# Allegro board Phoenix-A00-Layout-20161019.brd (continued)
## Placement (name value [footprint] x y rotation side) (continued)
D41  BAT54A-7-F_200mA  [SOT23_123]  225.41 246.13 90 top
DA4  AZ5125-02S.R7G  [SOT23_123]  192.44 12.91 0 top
DA5  AZ5125-02S.R7G  [SOT23_123]  171.86 24.72 180 top
DA6  AZ5125-02S.R7G  [SOT23_123]  232.32 243.41 180 top
DA7  AZ5125-01H  [SOD_523]  197.39 18.37 270 top
DF1  1N4148W-7-F_150mA  [SOD123]  198.66 222 180 top
DG1  BAV99-7-F_300mA  [SOT23_123]  162.99 229.87 90 top
DG2  BAV99-7-F_300mA  [SOT23_123]  169.85 229.87 90 top
DG3  BAV99-7-F_300mA  [SOT23_123]  166.42 229.87 90 top
DG4  1N4148W-7-F_150mA  [SOD123]  188.25 235.84 180 top
DG5  BAV99-7-F_300mA  [SOT23_123]  159.55 235.59 90 top
DG6  BAV99-7-F_300mA  [SOT23_123]  159.55 231.78 90 top
DG7  BAV99-7-F_300mA  [SOT23_123]  172.77 232.66 0 top
DG8  BAV99-7-F_300mA  [SOT23_123]  173.28 228.87 90 top
DIMM1  DDR IV_288P_15u_Black  [DDR4_288_67_5591X256]  223.94 91.72 180 top
DIMM2  DDR IV_288P_15u_Black  [DDR4_288_67_5591X256]  223.94 82.72 180 top
DO1  B0540W-7-F_0.5A  [SOD123_H57]  201.58 41.53 0 top
DO2  1N4148W-7-F_150mA  [SOD123]  182.41 235.84 180 top
DO3  1N4148W-7-F_150mA  [SOD123]  178.21 223.77 180 top
ECK1  470uF_EC_6.3V  [CE25D63H125]  31.15 170.31 0 top
ECK3  470uF_EC_6.3V  [CE25D63H125]  49.69 220.85 0 top
ECK4  120uF_EC_16V  [CE25D63H125]  71.03 237.74 0 top
ECK5  470uF_EC_6.3V  [CE25D63H125]  31.53 231.01 0 top
ECK6  470uF_EC_6.3V  [CE25D63H125]  31.78 216.92 0 top
ECK7  120uF_EC_16V  [CE25D63H125]  31.53 243.33 0 top
ECU2  470uF_EC_6.3V  [CE25D63H125]  138.29 230.76 0 top
ECU3  470uF_EC_6.3V  [CE25D63H125]  142.48 236.85 0 top
ECU6  220uF_EC_10V  [CE25D63H125]  132.44 19.93 0 top
ECU7  220uF_EC_10V  [CE25D63H125]  132.37 26.8 0 top
ECU9  470uF_EC_6.3V  [CE25D63H125]  59.22 69.93 0 top
ECU10  220uF_EC_10V  [CE25D63H125]  156.29 21.1 0 top
ECU13  470uF_EC_6.3V  [CE25D63H125]  98.03 251.33 0 top
ECX7  220uF_EC_16V  [CE25D63H125]  70.14 244.86 0 top
ECX10  470uF_EC_16V  [CE35D80H130]  50.83 238.25 0 top
ECX11  470uF_EC_6.3V  [CE25D63H125]  71.28 230.89 0 top
ECX12  220uF_EC_10V  [CE25D63H125]  71.28 224.03 0 top
EEPROM_G  M24C01-WMN6TP  [SOP8JA]  164.01 225.04 90 top
F2  1.5A_6V  [FS_70_83X53]  225.54 250.32 270 top
F6  1.5A_6V  [FS_70_83X53]  163.96 238.99 180 top
F_AUDIO  HDA_X1_GF_Black  [AUDIO_6_374X463]  186.32 12.64 180 top
F_USB2  USBX2_GF_Black  [USB4X2]  164.75 10.62 180 top
F_USB3  USB3X2_15u_Blue  [USB3X4_18_79]  143.75 13.01 0 top
FAN_CPU  Header_1X4_GF_Ivory  [HFAN_4_100_400X225_P2]  238.29 133.22 270 top
FAN_SYS  FAN_3P_T_Brown  [HFAN_3_100_300X224_C2]  197.01 227.35 0 top
FBA1  600_500mA  [0603_H37]  195.36 19.64 180 top
FBA2  600_500mA  [0603_H37]  195.36 20.91 180 top
FBA3  80_3A  [0805]  195.11 24.34 180 top
FBA4  600_500mA  [0603_H37]  188.63 31.83 0 top
FBA5  600_500mA  [0603_H37]  195.36 22.18 180 top
FBG1  600_1A  [0603_H37]  144.81 232.54 270 top
FBG2  600_1A  [0603]  155.75 219.84 180 top
FBK1  600_500mA  [0603]  65.95 182.88 180 top
FBK3  600_500mA  [0603]  51.6 184.15 90 top
FG1  1.1A_6V  [FS1311_H28]  201.46 247.14 90 top
FM1  MTG/ID4/OD7  [FD40]  28.61 252.98 0 top
FM2  MTG/ID4/OD7  [FD40]  5.7 41.48 180 bottom
FM3  MTG/ID4/OD7  [FD40]  28.61 252.98 180 bottom
FM4  MTG/ID4/OD7  [FD40]  230.23 26.49 180 bottom
FM5  MTG/ID4/OD7  [FD40]  5.14 39.47 0 top
FM7  MTG/ID4/OD7  [FD40]  229.27 25.4 0 top
FU2  3A_6V  [FS0805]  143.92 241.43 180 top
FU5  3A_6V  [FS0805]  154.21 11.64 270 top
FU6  3A_6V  [FS0805]  134.4 7.7 90 top
FU9  3A_6V  [FS0805]  64.93 70.1 0 top
FVS  TEST POINT  [FVS_DELL]  70.01 105.28 270 top
HDD_LED  LED ASSEMBLY_White  [LED_2_90_201X260]  197.5 10.97 0 top
HDMI  HDMI_R_19P_15u_Black  [HDMI_19_59_591X492]  211.29 248.13 180 top
HS_CLIP1  CLIP_2P  [HB9003]  38.97 147.34 270 top
HS_CLIP2  CLIP_2P  [HB9003]  75.57 101.58 270 top
INT_SPKR  Header_1X4_GF_Ivory  [HF5504]  163.28 53.29 0 top
IO_FBI7  120_3A  [0603]  175.67 24.21 180 top
IO_FBI8  120_3A  [0603]  175.67 25.48 180 top
IO_FBI9  60_3A  [0603_H37]  189.64 10.75 90 top
IO_FBI10  60_3A  [0603_H37]  188.37 10.75 90 top
IO_FBI11  60_3A  [0603_H37]  237.78 244.47 180 top
IO_FBI12  60_3A  [0603_H37]  237.78 243.08 180 top
IO_FBI13  100_2A  [0603_H37]  163.63 49.94 270 top
IO_FBI14  100_2A  [0603_H37]  165.03 49.94 270 top
KYBD_MOUSE  PS2-KBMS-2_GF  [PS2X2]  156.19 254.52 0 top
L13  120_400mA  [0603]  154.84 235.55 270 top
L14  120_400mA  [0603]  152.3 235.55 270 top
L15  120_400mA  [0603]  156.11 235.55 270 top
L16  120_400mA  [0603]  153.57 235.55 270 top
L60  2.2uH_115mA  [0603]  54.39 147.07 270 top
L61  2.2uH_115mA  [0603]  70.9 109.09 180 top
L62  2.2uH_115mA  [0603]  64.8 143 0 top
LG1  22_600mA  [0603_H37]  168.7 234.95 180 top
LG2  22_600mA  [0603_H37]  165.91 234.95 180 top
LG3  22_600mA  [0603_H37]  163.12 234.95 180 top
LL2  4.7uH_1A/1.35A  [1212H59]  117.89 221.23 270 top
LPC_DEBUG  Header_2X7_K10_GF_Black  [HH_2X7_79_O10]  7.91 156.08 270 top
LU1  CMC_90_330mA  [L4S12X20V_H43]  97.52 246.51 180 top
LU2  CMC_90_330mA  [L4S12X20V_H43]  97.52 243.97 180 top
LU4  CMC_90_330mA  [L4S12X20V_H43]  131.3 235.71 90 top
LU23  CMC_90_330mA  [L4S12X20V_H43]  42.83 74.55 0 top
LU24  CMC_90_330mA  [L4S12X20V_H43]  42.83 77.22 0 top
LU35  CMC_90_330mA  [L4S12X20V_H43]  133.84 235.71 90 top
LU36  CMC_90_330mA  [L4S12X20V_H43]  151.05 24.36 90 top
LU37  CMC_90_330mA  [L4S12X20V_H43]  148.51 24.36 90 top
M.2_SSD  NGFF_67P_GF_Black  [NGFF_75_20_862X232_KM]  113.39 123.85 180 top
MH1  Mounting Hole  [MH40X80_10_DELL_L4]  237.65 225.81 0 top
MH2  Mounting Hole  [MH_146_320_10_M2_P2_DELL_L4]  80.17 248.67 270 top
MH3  Mounting Hole  [MH40X80_10_DELL_L4]  8.65 248.67 0 top
MH4  Mounting Hole  [MH40X80_10_DELL_L4]  234.35 98.81 0 top
MH5  Mounting Hole  [MH40X80_10_DELL_L4]  86.35 98.81 0 top
MH6  Mounting Hole  [MH40X80_10_DELL_L4]  14.13 93.73 0 top
MH7  Mounting Hole  [MH40X80_10_DELL_L4]  80.17 30.34 0 top
MH8  Mounting Hole  [MH_146_320_10_M2_P2_DELL_L4]  234.35 34.89 0 top
MH21  Mounting Hole  [NP157X354_D8_SP]  104.15 168.18 90 top
MH22  Mounting Hole  [NP157X354_D8_SP]  104.14 206.18 90 top
NIC_USB  USBX2+RJ45_15u_Black  [USB4X2_RJ45P10_LED3]  112.5 249.53 180 top
NOREF  -  [unnamed]  239.43 237.49 0 top
NOREF#2  -  [#2]  86.01 125.22 0 top
NOREF#3  -  [#2]  204.5 1.43 90 top
NOREF#4  -  [#2]  78.39 42.16 0 top
NOREF#5  -  [unnamed]  20.23 252.48 0 top
NOREF#6  -  [#2]  0 253.69 0 top
NOREF#7  -  [unnamed]  228 13.84 0 top
NOREF#8  -  [#2]  7.91 16.76 0 top
NOREF#9  -  [#2]  117.84 53.35 0 top
P1  Header_1X2_GF  [H2M-1]  151.42 44.07 180 top
P2  Header_1X2_GF  [H2M-1]  140.5 44.07 180 top
P3  Header_1X2_GF  [H2M-1]  143.42 44.07 0 top
PAD1  Header_1X2_GF  [H2M-1]  36.23 252.86 0 top
PC1  100pF_NPO_16V  [C0402]  42.32 146.69 90 top
PC2  1uF_X7R_16V  [C0603]  97.57 136.14 90 top
PC17  4.7uF_X5R_6.3V  [C0603]  21.62 64.64 180 top
PC18  100nF_X5R_6.3V  [C0402]  20.86 65.79 180 top
PC21  220nF_X5R_6.3V  [C0402]  19.46 75.18 0 top
PC22  1uF_X5R_6.3V  [C0402]  17.43 76.2 180 top
PC24  4.7uF_X5R_6.3V  [C0603]  12.61 207.26 0 top
PC25  100nF_X5R_6.3V  [C0402]  12.61 206.12 0 top
PC26  4.7uF_X5R_6.3V  [C0603]  15.27 233.04 90 top
PC30  220nF_X5R_6.3V  [C0402]  7.27 208.41 270 top
PC32  10uF_X7R_16V  [C1206_H73]  203.49 63.88 90 top
PC33  100nF_X7R_16V  [C0402]  205.01 63.75 90 top
PC34  1uF_X7R_6.3V  [C0603]  209.08 73.79 90 top
PC35  1nF_X7R_16V  [C0402]  213.65 68.58 270 top
PC36  100nF_X7R_50V  [C0603]  208.69 70.48 90 top
PC37  2.2nF_X7R_50V  [C0603]  204.88 68.96 0 top
PC38  22uF_X5R_6.3V  [C0805]  169.96 75.18 180 top
PC39  22uF_X5R_6.3V  [C0805]  175.67 75.06 0 top
PC40  22uF_X5R_6.3V  [C0805]  143.67 96.52 90 top
PC41  33pF_NPO_50V  [C0402]  216.31 72.01 0 top
PC42  1nF_X7R_50V  [C0402]  218.73 72.01 0 top
PC43  22uF_X5R_4V  [C0603_H39]  162.72 73.41 90 top
PC44  22uF_X5R_4V  [C0603_H39]  165.01 75.31 0 top
PC45  22uF_X5R_4V  [C0603_H39]  161.2 73.41 90 top
PC46  22uF_X5R_4V  [C0603_H39]  155.35 64.52 180 top
PC47  10uF_X5R_6.3V  [C0805]  155.86 66.17 180 top
PC48  1uF_X7R_6.3V  [C0603]  149.26 71.12 90 top
PC49  10nF_X7R_16V  [C0402]  150.91 65.28 270 top
PC50  22uF_X5R_6.3V  [C0805]  155.48 75.31 180 top
PC57  100nF_X7R_16V  [C0402]  96.3 66.67 180 top
PC58  10uF_X7R_16V  [C1206_H73]  70.52 81.15 90 top
PC59  10uF_X7R_16V  [C1206_H73]  72.68 81.15 90 top
PC61  100nF_X7R_16V  [C0402]  61.37 79.12 180 top
PC62  1nF_X7R_16V  [C0402]  60.74 76.33 270 top
PC63  1uF_X5R_6.3V  [C0603]  60.36 81.28 270 top
PC64  100nF_X7R_25V  [C0603]  62.14 81.79 90 top
PC65  2.2nF_X7R_50V  [C0402]  72.3 87.5 0 top
PC66  22uF_X5R_6.3V  [C0805]  70.72 95.58 0 top
PC67  22uF_X5R_6.3V  [C0805]  73.82 90.04 90 top
PC68  22uF_X5R_6.3V  [C0805]  69.43 98.68 90 top
PC69  22uF_X5R_6.3V  [C0805]  72.17 90.04 90 top
PC70  22uF_X5R_6.3V  [C0805]  70.72 93.8 0 top
PC71  10uF_X7R_16V  [C1206_H73]  149.51 200.66 0 top
PC72  10nF_X7R_16V  [C0402]  61.37 77.72 180 top
PC73  1uF_X5R_6.3V  [C0402]  98.71 101.98 0 top
PC79  470pF_X7R_50V  [C0402]  5.62 225.04 180 top
PC80  4.7uF_X7R_16V  [C1206_H71]  6.51 214.63 270 top
PC81  1uF_X5R_16V  [C0603]  13.24 236.09 0 top
PC82  100nF_X7R_16V  [C0402]  15.27 239.78 90 top
PC83  100nF_X7R_16V  [C0402]  223.49 196.53 90 top
PC84  1uF_X7R_6.3V  [C0603]  228.51 185.6 180 top
PC85  470nF_X7R_16V  [C0603]  216.38 194.07 0 top
PC86  100nF_X5R_16V  [C0402]  214.22 195.24 180 top
PC87  470nF_X7R_16V  [C0603]  216.38 192.47 0 top
PC88  100nF_X5R_16V  [C0402]  214.22 191.33 180 top
PC89  220nF_X5R_16V  [C0402]  219.2 198.44 180 top
PC90  220nF_X5R_16V  [C0402]  224.63 198.95 90 top
PC91  470nF_X7R_16V  [C0603]  216.76 197.42 0 top
PC92  100nF_X5R_16V  [C0402]  214.22 196.25 0 top
PC93  4.7uF_X5R_6.3V  [C0603]  224.06 179.7 270 top
PC94  470nF_X5R_6.3V  [C0402]  221.2 182.82 180 top
PC95  470nF_X7R_16V  [C0603]  228.32 193.43 0 top
PC96  220pF_NPO_50V  [C0402]  216.76 188.02 180 top
PC97  82pF_NPO_50V  [C0402]  216.76 189.04 0 top
PC98  100nF_X5R_16V  [C0402]  229.78 196.22 90 top
PC99  3.3nF_X7R_50V  [C0402]  216.76 187.01 180 top
PC100  100nF_X7R_16V  [C0402]  212.19 186.63 180 top
PC101  470nF_X7R_16V  [C0603]  228.32 192.11 180 top
PC102  100nF_X5R_16V  [C0402]  230.75 192.32 0 top
PC103  220pF_NPO_50V  [C0402]  231.81 188.85 0 top
PC104  82pF_NPO_50V  [C0402]  228.32 189.93 180 top
PC105  3.3nF_X7R_50V  [C0402]  227.81 188.28 90 top
PC106  100nF_X7R_16V  [C0402]  229.46 187.77 0 top
PC107  2.2nF_X7R_50V  [C0402]  197.26 210.95 270 top
PC108  10uF_X7R_16V  [C1206_H73]  198.1 214.6 90 top
PC109  100nF_X7R_16V  [C0603]  220.25 207.39 270 top
PC110  1uF_X7R_16V  [C0603]  217.84 211.2 180 top
PC111  2.2nF_X7R_50V  [C0402]  207.17 198.75 270 top
PC114  2.2nF_X7R_50V  [C0402]  179.99 208.15 270 top
PC115  10uF_X7R_16V  [C1206_H73]  184.18 214.38 90 top
PC116  100nF_X7R_16V  [C0603]  193.96 207.9 270 top
PC117  1uF_X7R_16V  [C0603]  191.8 211.96 180 top
PC119  2.2nF_X7R_50V  [C0402]  189.39 191.01 270 top
PC121  10uF_X7R_16V  [C1206_H73]  170.59 214.5 90 top
PC122  2.2nF_X7R_50V  [C0402]  162.97 208.53 270 top
PC123  100nF_X7R_16V  [C0603]  176.94 204.09 270 top
PC124  1uF_X7R_16V  [C0603]  174.53 208.03 180 top
PC125  2.2nF_X7R_50V  [C0402]  173.9 186.44 270 top
PC128  22uF_X5R_6.3V  [C0805]  164.5 174.5 0 top
PC129  22uF_X5R_6.3V  [C0805]  169.45 174.5 0 top
PC130  22uF_X5R_6.3V  [C0805]  174.4 174.5 0 top
PC131  22uF_X5R_6.3V  [C0805]  179.74 174.5 0 top
PC132  22uF_X5R_6.3V  [C0805]  184.69 174.5 0 top
PC133  22uF_X5R_6.3V  [C0805]  166.28 151.26 270 top
PC134  22uF_X5R_6.3V  [C0805]  164.24 151.26 270 top
PC135  22uF_X5R_6.3V  [C0805]  170.34 151.26 270 top
PC136  22uF_X5R_6.3V  [C0805]  168.31 151.26 270 top
PC137  22uF_X5R_6.3V  [C0805]  166.28 147.83 270 top
PC138  22uF_X5R_6.3V  [C0805]  164.24 147.83 270 top
PC139  22uF_X5R_6.3V  [C0805]  168.31 147.83 270 top
PC140  22uF_X5R_6.3V  [C0805]  170.34 147.83 270 top
PC141  22uF_X5R_6.3V  [C0805]  170.34 144.27 90 top
PC142  22uF_X5R_6.3V  [C0805]  168.31 144.27 90 top
PC143  22uF_X5R_6.3V  [C0805]  164.24 144.27 90 top
PC144  22uF_X5R_6.3V  [C0805]  166.28 144.27 90 top
PC148  22uF_X5R_4V  [C0603]  169.07 141.99 180 top
PC149  22uF_X5R_4V  [C0603]  166.02 141.99 0 top
PC150  22uF_X5R_4V  [C0603]  163.23 141.99 180 top
PC151  10uF_X7R_16V  [C1206_H73]  232.19 170.05 90 top
PC152  2.2nF_X7R_50V  [C0402]  226.6 170.81 90 top
PC153  100nF_X7R_16V  [C0603]  229.4 157.61 180 top
PC154  1uF_X7R_16V  [C0603]  229.52 161.67 180 top
PC155  2.2nF_X7R_50V  [C0402]  212.25 160.78 270 top
PC158  47uF_X5R_6.3V  [C0805]  204.5 147.45 270 top
PC159  47uF_X5R_6.3V  [C0805]  204.5 154.56 270 top
PC160  47uF_X5R_6.3V  [C0805]  204.38 161.42 270 top
PC161  47uF_X5R_6.3V  [C0805]  204.38 168.27 270 top
PC162  47uF_X5R_6.3V  [C0805]  174.79 151.26 270 top
PC166  10uF_X7R_16V  [C1206_H73]  232.19 146.18 270 top
PC167  2.2nF_X7R_50V  [C0402]  228.25 152.91 90 top
PC168  47uF_X5R_6.3V  [C0805]  172.75 151.26 270 top
PC169  47uF_X5R_6.3V  [C0805]  174.79 147.83 270 top
PC170  47uF_X5R_6.3V  [C0805]  172.75 147.83 270 top
PC171  47uF_X5R_6.3V  [C0805]  174.79 144.27 270 top
PC172  47uF_X5R_6.3V  [C0805]  172.75 144.27 270 top
PC173  100nF_X7R_16V  [C0603]  228.76 139.95 180 top
PC174  1uF_X7R_16V  [C0603]  228.89 144.78 180 top
PC175  2.2nF_X7R_50V  [C0402]  211.87 142.62 270 top
PC178  1uF_X7R_6.3V  [C0603]  143.8 202.31 90 top
PC179  270uF_CP_16V  [CE35D80H90]  151.04 205.99 0 top
PC180  100nF_X7R_50V  [C0603]  141.38 201.8 0 top
PC181  1nF_X7R_16V  [C0402]  140.24 193.93 270 top
PC182  2.2nF_X7R_50V  [C0402]  152.05 193.04 0 top
PC183  22uF_X5R_6.3V  [C0805]  154.21 179.32 270 top
PC184  33pF_NPO_50V  [C0402]  145.32 193.93 90 top
PC185  100nF_X7R_16V  [C0402]  144.05 192.02 180 top
PC186  47uF_X5R_6.3V  [C0805]  162.34 144.27 270 top
PC187  47uF_X5R_6.3V  [C0805]  158.53 147.57 90 top
PC188  47uF_X5R_6.3V  [C0805]  156.75 147.57 90 top
PC189  47uF_X5R_6.3V  [C0805]  158.53 144.27 270 top
PC190  47uF_X5R_6.3V  [C0805]  156.75 144.27 270 top
PC191  47uF_X5R_6.3V  [C0805]  160.43 144.27 270 top
PC192  22uF_X5R_4V  [C0603_H39]  162.34 147.32 90 top
PC193  22uF_X5R_4V  [C0603_H39]  160.56 147.32 90 top
PC195  22uF_X5R_6.3V  [C0805]  105.82 143.76 180 top
PC196  22uF_X5R_6.3V  [C0805]  105.82 145.54 180 top
PC197  1nF_X7R_16V  [C0402]  106.08 136.65 0 top
PC198  100nF_X7R_16V  [C0402]  105.82 142.37 180 top
PC199  220nF_X7R_16V  [C0603]  115.6 148.34 0 top
PC200  1nF_X7R_50V  [C0402]  110.78 148.34 0 top
PC201  22uF_X5R_6.3V  [C0805]  117.89 149.99 90 top
PC202  22uF_X5R_6.3V  [C0805]  116.11 150.62 90 top
PC203  22uF_X5R_6.3V  [C0805]  160.31 151.26 90 top
PC204  22uF_X5R_6.3V  [C0805]  162.34 151.26 90 top
PC206  22nF_X7R_50V  [C0402]  111.67 139.06 270 top
PC207  10uF_X7R_16V  [C1206_H73]  195.94 214.6 90 top
PC208  10uF_X7R_16V  [C1206_H73]  182.02 214.38 90 top
PC209  10uF_X7R_16V  [C1206_H73]  168.44 214.5 90 top
PC210  10uF_X7R_16V  [C1206_H73]  232.19 163.7 270 top
PC211  10uF_X7R_16V  [C1206_H73]  232.19 152.27 90 top
PC229  100nF_X7R_16V  [C0402]  100.11 73.15 90 top
PC230  10uF_X7R_16V  [C1206_H73]  105.44 74.04 90 top
PC231  10uF_X7R_16V  [C1206_H73]  103.28 74.04 90 top
PC234  100nF_X7R_25V  [C0603]  100.24 67.56 90 top
PC236  22uF_X5R_6.3V  [C0805]  88.68 71.88 180 top
PC240  10nF_X7R_25V  [C0402]  106.46 68.07 180 top
PC241  22nF_X7R_16V  [C0402]  106.46 71.12 0 top
PC258  1uF_X7R_6.3V  [C0603]  94.01 245.75 270 top
PC261  1uF_X7R_6.3V  [C0603]  66.71 73.41 0 top
PC262  1nF_X7R_16V  [C0402]  63.53 76.45 180 top
PC293  22uF_X5R_4V  [C0603_H39]  173.77 141.99 0 top
PC294  22uF_X5R_4V  [C0603_H39]  116.11 143.13 270 top
PC295  22uF_X5R_4V  [C0603_H39]  122.46 151.38 0 top
PC296  22uF_X5R_4V  [C0603_H39]  117.38 143.13 270 top
PC297  22uF_X5R_4V  [C0603_H39]  121.32 150.11 0 top
PC298  22uF_X5R_4V  [C0603_H39]  159.67 141.99 0 top
PC300  100nF_X7R_16V  [C0402]  104.62 37.75 0 top
PC301  100nF_X7R_16V  [C0402]  8.29 38.73 90 top
PC302  100nF_X7R_16V  [C0402]  13.5 42.8 90 top
PC303  100nF_X7R_16V  [C0402]  99.6 49.4 180 top
PC304  10nF_X7R_25V  [C0402]  22.1 45.19 0 top
PC305  100nF_X7R_16V  [C0402]  22.1 44.17 0 top
PC308  100nF_X7R_16V  [C0402]  16.16 46.61 270 top
PC309  100nF_X7R_16V  [C0402]  61.25 55.12 180 top
PC310  22uF_X5R_6.3V  [C0805]  95.54 93.47 180 top
PC311  22uF_X5R_6.3V  [C0805]  88.68 73.66 180 top
PC312  22uF_X5R_6.3V  [C0805]  96.17 95.99 90 top
PC313  22uF_X5R_6.3V  [C0805]  88.68 75.44 180 top
PC315  220nF_X7R_16V  [C0603]  112.17 30.48 180 top
PC316  1uF_X5R_16V  [C0603]  58.58 34.16 90 top
PC319  100nF_X7R_16V  [C0402]  62.01 34.54 90 top
PC320  1uF_X5R_16V  [C0603]  59.85 34.16 270 top
PC321  1nF_X7R_16V  [C0402]  50.96 33.78 180 top
PC322  10uF_X5R_16V  [C0805]  48.29 31.12 180 top
PC323  10uF_X7R_16V  [C1206_H73]  36.36 43.05 90 top
PC324  10uF_X7R_16V  [C1206_H73]  50.83 43.05 90 top
PC325  100nF_X7R_16V  [C0402]  46.77 55.88 270 top
PC326  100nF_X7R_16V  [C0402]  38.01 44.32 90 top
PC327  100nF_X7R_16V  [C0402]  49.31 43.18 90 top
PC328  100nF_X7R_50V  [C0603]  40.42 52.96 0 top
PC329  100nF_X7R_50V  [C0603]  49.82 52.07 180 top
PC330  2.2nF_X7R_50V  [C0402]  59.47 52.83 90 top
PC331  22uF_X5R_6.3V  [C0805]  13.88 47.5 180 top
PC332  2.2nF_X7R_50V  [C0402]  36.36 47.88 0 top
PC333  22uF_X5R_6.3V  [C0805]  61.25 56.39 180 top
PC334  22pF_NPO_25V  [C0402]  46.52 46.48 90 top
PC335  22pF_NPO_25V  [C0402]  43.34 46.61 90 top
PC336  1uF_X7R_6.3V  [C0603]  43.59 55.12 180 top
PC337  1uF_X7R_6.3V  [C0603]  45.63 56.01 90 top
PC338  1uF_X7R_6.3V  [C0603]  45.37 46.48 270 top
PC339  1nF_X7R_16V  [C0402]  41.69 49.66 270 top
PC340  100nF_X7R_16V  [C0402]  8.29 41.78 270 top
PC341  100nF_X7R_16V  [C0402]  6.64 41.78 0 top
PC342  2.2nF_X7R_50V  [C0402]  97.95 75.82 0 top
PC343  22nF_X7R_16V  [C0402]  16.92 65.15 0 top
PC344  100nF_X7R_16V  [C0402]  50.07 58.55 270 top
PC345  10uF_X5R_6.3V  [C0805]  48.42 58.67 270 top
PC346  10uF_X5R_6.3V  [C0805]  7.91 56.77 270 top
PC347  100nF_X7R_16V  [C0402]  50.2 63.37 270 top
PC348  15pF_NPO_50V  [C0402]  109.13 69.09 0 top
PC349  100nF_X5R_6.3V  [C0402]  106.46 69.09 0 top
PC350  1uF_X5R_16V  [C0603]  102.78 142.49 0 top
PCE1  270uF_CP_16V  [CE35D80H90]  172.88 62.74 0 top
PCE2  820uF_CP_2.5V  [CE25D63H95]  166.4 70.36 0 top
PCE3  820uF_CP_2.5V  [CE25D63H95]  173.39 70.48 0 top
PCE4  820uF_CP_2.5V  [CE25D63H95]  180.5 70.48 0 top
PCE7  820uF_CP_2.5V  [CE25D63H95]  65.49 95.88 0 top
PCE8  220uF_EC_16V  [CE25D63H125]  8.67 237.64 0 top
PCE12  270uF_CP_16V  [CE35D80H90]  189.77 216.92 0 top
PCE13  270uF_CP_16V  [CE35D80H90]  176.18 213.74 0 top
PCE14  270uF_CP_16V  [CE35D80H90]  230.03 176.4 0 top
PCE15  820uF_CP_2.5V  [CE25D63H95]  186.85 183.39 0 top
PCE16  820uF_CP_2.5V  [CE25D63H95]  163.99 179.32 0 top
PCE17  820uF_CP_2.5V  [CE25D63H95]  174.4 179.32 0 top
PCE18  820uF_CP_2.5V  [CE25D63H95]  169.32 183.9 0 top
PCE19  820uF_CP_2.5V  [CE25D63H95]  181.26 179.32 0 top
PCE21  820uF_CP_2.5V  [CE25D63H95]  207.93 144.02 0 top
PCE22  820uF_CP_2.5V  [CE25D63H95]  207.93 164.85 0 top
PCE23  820uF_CP_2.5V  [CE25D63H95]  207.93 171.7 0 top
PCE24  820uF_CP_2.5V  [CE25D63H95]  207.93 157.99 0 top
PCE25  820uF_CP_2.5V  [CE25D63H95]  207.93 151.13 0 top
PCE26  820uF_CP_2.5V  [CE25D63H95]  144.43 185.55 0 top
PCE27  820uF_CP_2.5V  [CE25D63H95]  149.77 179.58 0 top
PCE28  820uF_CP_2.5V  [CE25D63H95]  120.91 146.05 0 top
PCE30  220uF_EC_16V  [CE25D63H125]  17.69 42.42 270 top
PCE31  470uF_EC_6.3V  [CE25D63H125]  12.86 62.87 0 top
PCE32  470uF_EC_6.3V  [CE25D63H125]  44.25 61.99 0 top
PCE33  270uF_CP_16V  [CE35D80H90]  66.71 33.27 0 top
PCE34  270uF_CP_16V  [CE35D80H90]  42.07 41.28 270 top
PCE35  560uF_CP_6.3V  [CE25D63H95]  19.97 60.58 0 top
PCE36  560uF_CP_6.3V  [CE25D63H95]  26.83 60.58 0 top
PCE37  560uF_CP_6.3V  [CE25D63H95]  66.33 58.04 0 top
PD2  LBAT54HT1G_200mA  [SOD_323_H43_1]  18.32 77.6 0 top
PD3  B130LAW-7-F_1A  [SOD123]  7.02 233.17 0 top
PD5  B340A-13-F_3A  [SMA]  53.75 30.61 0 top
PD6  B130LAW-7-F_1A  [SOD123]  9.81 40.64 270 top
PD8  LBAT54HT1G_200mA  [SOD_323_H43_1]  51.98 35.18 0 top
PFB2  30_6A  [0805]  166.02 62.87 180 top
PFB3  30_6A  [0805]  166.02 64.64 180 top
PFB4  30_6A  [0805]  71.79 77.22 270 top
PFB10  30_6A  [0805]  59.6 40.77 180 top
PFB11  30_6A  [0805]  59.6 42.54 180 top
PFB12  30_6A  [0805]  110.4 73.15 0 top
PJP2  SHORT-PAD-10  [R0402_S10MIL_MVB]  218.73 72.9 0 top
PJP4  SHORT-PAD-10  [R0402_S10MIL_MVB]  68.49 76.45 180 top
PJP9  SHORT PAD  [SHORTPAD_R10X16]  202.98 202.06 270 bottom
PJP10  SHORT PAD  [SHORTPAD_R10X16]  202.98 201.04 270 bottom
PJP11  SHORT PAD  [SHORTPAD_R10X16]  184.06 193.68 270 bottom
PJP12  SHORT PAD  [SHORTPAD_R10X16]  184.06 192.66 270 bottom
PJP13  SHORT PAD  [SHORTPAD_R10X16]  166.66 193.93 270 bottom
PJP14  SHORT PAD  [SHORTPAD_R10X16]  166.66 193.17 270 bottom
PJP15  SHORT PAD  [SHORTPAD_R10X16]  218.09 168.66 0 bottom
PJP16  SHORT PAD  [SHORTPAD_R10X16]  217.46 168.66 0 bottom
PJP17  SHORT PAD  [SHORTPAD_R10X16]  218.22 149.86 0 bottom
PJP18  SHORT PAD  [SHORTPAD_R10X16]  217.46 149.86 0 bottom
PJP19  SHORT PAD  [SHORTPAD_R10X16]  141.13 191.52 0 top
PJP20  SHORT PAD  [SHORTPAD_R10X16]  119.41 144.91 90 bottom
PJP30  SHORT PAD  [SHORTPAD_R10X16]  18.83 58.93 180 bottom
PJP31  SHORT PAD  [SHORTPAD_R10X16]  66.2 57.15 90 top
PJP32  SHORT PAD  [SHORTPAD_R10X16]  89.06 70.61 180 top
PL2  680nH_40A/27A  [CK_272X185_461X382_H343]  190.15 69.72 180 top
PL3  1uH_22A/11A  [L_2_244_295X268]  67.6 87.83 90 top
PL4  100uH_1.3A/0.8A  [2424H45]  8.16 228.85 0 top
PL5  360nH_50A/43A  [CK_260X165_461X382]  201 201.45 270 top
PL6  1uH_18A/15A  [CK45X44S90_H236]  218.22 216.79 180 top
PL7  360nH_50A/43A  [CK_260X165_461X382]  183.42 193.07 270 top
PL8  360nH_50A/43A  [CK_260X165_461X382]  165.77 193.57 270 top
PL9  360nH_50A/43A  [CK_260X165_461X382]  217.59 168.08 180 top
PL10  360nH_50A/43A  [CK_260X165_461X382]  217.6 149.29 180 top
PL11  680nH_25A/15.5A  [L_2_244_299X268]  151.54 187.71 270 top
PL12  1.5uH_27.5A/15A  [L4540]  22.77 51.69 0 top
PL13  2.2uH_14A/8A  [L_2_244_295X268]  63.66 50.04 90 top
PL15  3.3uH_13.5A/6A  [L_2_244_299X268]  94.9 71.63 180 top
PPID  Type_T_PPID_Label  [LOGO_DELL_PPID]  101.63 104.9 0 top
PQ2  SI3443CDV-T1-GE3  [TSOP6QI]  24.04 68.71 270 top
PQ3  DMN65D8LDW-7  [SOT363M]  99.98 135.89 0 top
PQ4  DMN65D8LDW-7  [SOT363M]  99.98 138.43 180 top
PQ7  AO3415AL  [SOT23_GSD]  20.1 68.83 90 top
PQ9  DMN65D8L-7  [SOT23_GSD]  14.64 75.18 270 top
PQ11  AO3415AL  [SOT23_GSD]  10.45 209.93 90 top
PQ13  SI3443CDV-T1-GE3  [TSOP6QI]  14 210.19 180 top
PQ15  AON6338FH  [DFN_8_50_238]  199.42 65.41 180 top
PQ16  DMN65D8L-7  [SOT23_GSD]  225.41 72.14 90 top
PQ17  AON6334FH  [DFN_8_50_238]  199.93 71.75 90 top
PQ19  DMN65D8LDW-7  [SOT363M]  221.9 72.39 180 top
PQ20  MMDT3904-7-F  [SOT363V]  152.69 64.01 270 top
PQ21  DMN65D8L-7  [SOT23_GSD]  96.17 64.52 0 top
PQ22  DMN65D8LDW-7  [SOT363M]  100.36 63.88 0 top
PQ23  AO3420L  [SOT23_GSD]  99.47 96.27 0 top
PQ24  DMN65D8LDW-7  [SOT363M]  98.71 99.75 90 top
PQ29  AON6338FH  [DFN_8_50_238]  202.09 212.73 0 top
PQ30  AON6334FH  [DFN_8_50_238]  209.7 208.79 90 top
PQ31  AON6334FH  [DFN_8_50_238]  209.7 202.82 90 top
PQ32  AON6338FH  [DFN_8_50_238]  183.8 208.16 0 top
PQ33  AON6334FH  [DFN_8_50_238]  192.3 203.2 90 top
PQ34  AON6334FH  [DFN_8_50_238]  192.18 194.94 90 top
PQ35  AON6338FH  [DFN_8_50_238]  166.78 208.16 0 top
PQ36  AON6334FH  [DFN_8_50_238]  174.52 190.5 90 top
PQ37  AON6334FH  [DFN_8_50_238]  174.52 199.52 90 top
PQ38  AON6338FH  [DFN_8_50_238]  227.62 166.88 270 top
PQ39  AON6334FH  [DFN_8_50_238]  216.08 158.7 0 top
PQ40  AON6334FH  [DFN_8_50_238]  222.18 158.7 0 top
PQ41  AON6338FH  [DFN_8_50_238]  227.74 149.1 270 top
PQ42  AON6334FH  [DFN_8_50_238]  215.44 140.53 0 top
PQ43  AON6334FH  [DFN_8_50_238]  221.54 140.53 0 top
PQ44  AON6934A  [DFN_7_50_205X219]  149.62 196.6 270 top
PQ45  FDMS3604S  [MOS_7_197X236]  149.64 196.6 270 top
PQ46  DMN65D8L-7  [SOT23_GSD]  117.89 153.67 270 top
PQ47  MMBT3904-7-F  [SOT23_BEC]  121.32 154.05 90 top
PQ48  AON6338FH  [DFN_8_50_238]  111.92 144.78 90 top
PQ49  DMN65D8LDW-7  [SOT363M]  104.05 138.94 270 top
PQ50  AOD558  [TO252_GDS]  12.35 51.82 180 top
PQ51  AOD558  [TO252_GDS]  59.47 60.83 270 top
PQ52  DMN65D8LDW-7  [SOT363M]  39.02 61.47 0 top
PQ53  AON7401L  [SO8_FL4]  56.04 36.45 180 top
PQ54  AOD558  [TO252_GDS]  103.03 32.51 90 top
PQ55  DMN65D8LDW-7  [SOT363M]  118.14 37.97 180 top
PQ57  DMN65D8L-7  [SOT23_GSD]  47.53 33.78 0 top
PQ58  AON6338FH  [DFN_8_50_238]  32.42 44.19 180 top
PQ59  AON6338FH  [DFN_8_50_238]  55.02 43.18 180 top
PQ60  AON6334FH  [DFN_8_50_238]  32.93 51.31 90 top
PQ61  AON6334FH  [DFN_8_50_238]  56.04 50.8 180 top
PQ71  DMN65D8L-7  [SOT23_GSD]  12.86 39.75 90 top
PQ72  MMDT3904-7-F  [SOT363V]  232.34 58.8 0 top
PQ76  MMBT3904-7-F  [SOT23_BEC]  235.87 59.82 270 top
PQ78  DMN65D8LDW-7  [SOT363M]  63.28 73.79 0 top
PQ79  MMDT3904-7-F  [SOT363V]  106.33 63.5 180 top
PR8  6.04K_1%  [R0402]  41.31 146.69 90 top
PR11  2.8K_1%  [R0402]  41.82 148.21 0 top
PR12  0_5%  [R0402]  39.78 123.57 0 top
PR14  100_1%  [R0402]  102.27 137.03 90 top
PR15  10K_5%  [R0402]  102.27 139.7 90 top
PR17  22K_5%  [R0402]  232.95 60.58 0 top
PR22  10K_5%  [R0402]  232.95 61.47 180 top
PR24  1.5K_1%  [R0402]  16.92 73.66 90 top
PR25  10K_1%  [R0402]  19.46 76.2 0 top
PR26  4.7K_1%  [R0402]  17.43 75.18 0 top
PR27  1K_5%  [R0402]  22.28 71.53 90 top
PR28  1K_5%  [R0402]  21.27 71.53 90 top
PR30  10_1%  [R0402]  18.45 72.77 0 top
PR31  1.5K_1%  [R0402]  6.26 208.41 90 top
PR32  1K_5%  [R0402]  14.13 233.04 90 top
PR34  20K_5%  [R0402]  230.03 57.4 270 top
PR35  8.2K_1%  [R0402]  6.76 209.93 0 top
PR36  10_1%  [R0402]  8.29 209.42 270 top
PR39  2.2_5%  [R0603]  207.81 73.79 90 top
PR40  2.2_5%  [R0805]  209.58 68.33 180 top
PR41  10K_5%  [R0402]  222.16 70.61 180 top
PR42  10K_5%  [R0402]  216.31 69.85 180 top
PR43  10K_5%  [R0402]  214.66 68.58 90 top
PR44  2.2_5%  [R0805]  205.52 67.06 180 top
PR45  10K_5%  [R0402]  203.36 67.31 90 top
PR46  200K_1%  [R0402]  213.27 73.91 0 top
PR47  2.2_5%  [R0805]  205.27 71.37 90 top
PR48  110K_1%  [R0402]  216.31 68.96 0 top
PR49  4.7K_5%  [R0402]  103.03 95.5 225 top
PR50  7.5K_0.5%  [R0402]  216.31 72.9 0 top
PR51  0_5%  [R0402]  216.31 73.79 0 top
PR52  10.2K_0.5%  [R0402]  216.31 71.12 0 top
PR53  1K_1%  [R0402]  158.53 69.98 90 top
PR54  4.7K_1%  [R0402]  150.91 63.25 90 top
PR55  1K_1%  [R0402]  159.55 69.98 270 top
PR56  100_5%  [R0402]  159.29 73.79 0 top
PR57  1.5K_1%  [R0402]  152.69 66.42 0 top
PR61  10K_5%  [R0402]  97.77 62.69 90 top
PR65  SHORT-PAD-10  [R0402_S10MIL_MVB]  94.27 66.67 180 top
PR67  75K_1%  [R0402]  69.88 77.85 0 top
PR68  10K_1%  [R0402]  61.76 76.33 90 top
PR69  51_1%  [R0402]  223.93 182.12 270 top
PR70  10K_5%  [R0402]  63.53 75.56 0 top
PR71  2.2_5%  [R0805]  72.93 85.34 270 top
PR73  2.61K_1%  [R0402]  68.49 75.44 0 top
PR74  10K_1%  [R0402]  66.2 76.45 180 top
PR75  0_1%  [R0402]  66.2 75.44 0 top
PR76  10K_5%  [R0402]  100.49 98.93 270 top
PR77  10K_5%  [R0402]  96.55 101.98 0 top
PR78  10_1%  [R0402]  96.3 100.08 0 top
PR87  270m_1%  [R0603]  9.05 216.28 180 top
PR88  3.92K_1%  [R0402]  14.26 238.76 90 top
PR89  1.87K_1%  [R0402]  4.99 220.22 90 top
PR90  16.2K_1%  [R0402]  4.99 218.19 270 top
PR91  510K_1%  [R0402]  222.47 198.95 270 top
PR92  110K_1%  [R0402]  222.47 196.53 90 top
PR93  69.8K_1%  [R0402]  219.55 177.74 90 top
PR94  143K_1%  [R0402]  218.41 177.74 90 top
PR95  174K_1%  [R0402]  217.27 177.74 90 top
PR96  69.8K_1%  [R0402]  216.12 177.74 90 top
PR97  73.2K_1%  [R0402]  214.98 177.74 90 top
PR98  2.2_5%  [R0603]  228.51 184.33 0 top
PR99  0_5%  [R0402]  217.27 179.77 90 top
PR100  18.2K_1%  [R0402]  219.55 184.85 90 top
PR101  1.37K_1%  [R0402]  213.96 194.12 180 top
PR102  453_1%  [R0402]  219.55 179.77 90 top
PR103  3.16K_1%  [R0402]  218.41 179.77 90 top
PR104  464_1%  [R0402]  216.12 179.77 90 top
PR105  1.2K_1%  [R0402]  214.98 179.77 90 top
PR106  680_1%  [R0402]  216.76 195.24 180 top
PR107  200_1%  [R0402]  214.98 182.31 90 top
PR108  13.7K_1%  [R0402]  214.98 184.85 90 top
PR109  100_1%  [R0402]  216.12 182.31 90 top
PR110  18.2K_1%  [R0402]  216.12 184.85 90 top
PR111  0_5%  [R0402]  217.27 182.31 90 top
PR112  3.32K_1%  [R0402]  217.27 184.85 90 top
PR113  174_1%  [R0402]  218.41 182.31 90 top
PR114  18.7K_1%  [R0402]  218.41 184.85 90 top
PR115  110_1%  [R0402]  219.55 182.31 90 top
PR116  1.37K_1%  [R0402]  213.96 192.47 180 top
PR117  680_1%  [R0402]  216.76 191.3 180 top
PR118  2.2_5%  [R0402]  219.17 199.45 0 top
PR119  487K_1%  [R0402]  219.81 196.53 270 top
PR120  2.2_5%  [R0402]  223.49 198.95 270 top
PR121  453K_1%  [R0402]  224.51 196.53 270 top
PR122  100K_1%  [R0402]  228.57 186.75 180 top
PR123  1.37K_1%  [R0402]  214.22 197.47 180 top
PR124  0_5%  [R0402]  221.2 181.8 0 top
PR125  12.4K_1%  [R0402]  220.7 180.28 270 top
PR126  680_1%  [R0402]  216.76 196.25 180 top
PR127  1_5%  [R0402]  221.58 184.85 270 top
PR128  6.49K_1%  [R0402]  220.7 178.24 90 top
PR129  8.45K_1%  [R0402]  220.7 184.85 90 top
PR130  45.3_1%  [R0402]  227.24 182.12 90 top
PR131  100_1%  [R0402]  226.22 182.12 270 top
PR132  75_1%  [R0402]  225.2 182.12 270 top
PR133  0_5%  [R0402]  221.71 180.28 90 top
PR134  15.8K_1%  [R0402]  221.71 178.24 270 top
PR135  7.5K_1%  [R0402]  222.92 178.31 90 top
PR136  13K_1%  [R0402]  222.6 184.85 90 top
PR137  10K_1%  [R0402]  216.76 190.18 180 top
PR138  51_5%  [R0402]  225.84 186.56 90 top
PR139  10_5%  [R0402]  224.95 185.67 90 top
PR140  0_5%  [R0402]  223.68 185.29 90 top
PR141  10K_5%  [R0402]  221.46 198.95 90 top
PR142  10K_1%  [R0402]  214.22 188.02 180 top
PR143  31.6K_1%  [R0402]  214.22 190.18 180 top
PR144  0_5%  [R0402]  214.22 189.04 180 top
PR145  1.33K_1%  [R0402]  230.73 194.5 0 top
PR146  100_1%  [R0402]  214.09 186.63 0 top
PR147  680_1%  [R0402]  228.06 194.63 0 top
PR148  SHORT-PAD-10  [R0402_S10MIL_MVB]  212.95 184.59 90 top
PR149  SHORT-PAD-10  [R0402_S10MIL_MVB]  211.62 184.66 90 top
PR150  100_1%  [R0402]  212.19 188.02 0 top
PR151  1.33K_1%  [R0402]  230.75 193.41 0 top
PR152  10K_1%  [R0402]  232.44 187.32 90 top
PR153  SHORT-PAD-10  [R0402_S10MIL_MVB]  231.3 184.78 90 top
PR154  29.4K_1%  [R0402]  230.35 190.94 0 top
PR155  0_5%  [R0402]  230.35 189.93 180 top
PR156  680_1%  [R0402]  228.32 190.94 0 top
PR157  100_1%  [R0402]  231.3 186.82 270 top
PR158  100_1%  [R0402]  229.46 188.79 180 top
PR159  10.5K_1%  [R0402]  214.22 198.79 180 top
PR160  10K_1%  [R0402]  228.32 195.77 0 top
PR161  SHORT-PAD-10  [R0402_S10MIL_MVB]  232.32 184.78 90 top
PR162  649K_1%  [R0402]  216.76 198.87 180 top
PR163  0_5%  [R0402]  218.79 196.53 90 top
PR164  649K_1%  [R0402]  225.59 196.6 270 top
PR165  10.5K_1%  [R0402]  230.79 196.22 90 top
PR166  0_5%  [R0402]  225.59 199.01 270 top
PR167  2.2_5%  [R0805]  197.39 208.79 0 top
PR168  2.2_5%  [R0805]  206.66 212.6 180 top
PR169  2.2_5%  [R0603]  220.25 210.57 90 top
PR170  2.2_5%  [R0805]  217.46 206.88 180 top
PR171  10K_5%  [R0402]  205.52 209.55 270 top
PR172  2.2_5%  [R0805]  209.65 198.73 0 top
PR173  2.2_5%  [R0805]  187.74 206.88 270 top
PR174  2.2_5%  [R0603]  193.84 212.72 90 top
PR175  2.2_5%  [R0805]  191.3 207.26 180 top
PR176  2.2_5%  [R0805]  179.99 205.36 270 top
PR177  10K_5%  [R0402]  187.74 204.09 270 top
PR178  2.2_5%  [R0805]  191.68 191.01 0 top
PR179  2.2_5%  [R0805]  162.97 205.74 270 top
PR180  2.2_5%  [R0603]  176.69 208.15 90 top
PR181  2.2_5%  [R0805]  174.15 203.45 180 top
PR182  2.2_5%  [R0805]  170.98 205.23 270 top
PR183  10K_5%  [R0402]  169.58 203.83 270 top
PR184  2.2_5%  [R0805]  176.18 186.44 0 top
PR185  2.2_5%  [R0805]  225.08 171.58 270 top
PR186  2.2_5%  [R0805]  226.22 160.53 90 top
PR187  2.2_5%  [R0603]  233.46 160.27 0 top
PR188  2.2_5%  [R0805]  226.22 156.46 90 top
PR189  10K_5%  [R0402]  225.2 163.19 180 top
PR190  2.2_5%  [R0805]  212.25 157.61 270 top
PR191  2.2_5%  [R0805]  225.71 143.26 90 top
PR192  2.2_5%  [R0805]  226.09 152.91 180 top
PR193  2.2_5%  [R0603]  232.06 143.13 0 top
PR194  2.2_5%  [R0805]  225.71 139.45 90 top
PR195  10K_5%  [R0402]  225.33 145.54 180 top
PR196  2.2_5%  [R0805]  211.49 139.57 270 top
PR197  2.2_5%  [R0603]  145.19 202.31 90 top
PR198  10K_5%  [R0402]  138.97 196.98 90 top
PR199  2.2_5%  [R0805]  141.38 203.71 0 top
PR200  2.2_5%  [R0805]  144.18 199.01 270 top
PR201  10K_5%  [R0402]  145.7 199.01 90 top
PR202  10K_5%  [R0402]  141.26 193.93 90 top
PR203  39K_1%  [R0402]  144.31 196.47 180 top
PR204  56K_1%  [R0402]  139.23 193.93 90 top
PR205  2.2_5%  [R0805]  154.08 194.18 90 top
PR206  10_1%  [R0402]  145.58 191.52 90 top
PR207  4.99K_1%  [R0402]  144.31 193.93 270 top
PR208  SHORT-PAD-10  [R0402_S10MIL_MVB]  144.05 191.01 0 top
PR209  10K_1%  [R0402]  142.27 193.93 270 top
PR210  0_5%  [R0402]  143.29 193.93 270 top
PR211  10_1%  [R0402]  142.27 191.52 90 top
PR212  10K_5%  [R0402]  118.02 156.21 0 top
PR213  1.5K_1%  [R0402]  120.05 151.38 180 top
PR214  2.2_5%  [R0603]  102.78 143.76 0 top
PR215  10K_5%  [R0402]  104.05 136.65 0 top
PR216  10K_5%  [R0402]  103.16 141.27 0 top
PR217  100_1%  [R0402]  113.7 148.84 270 top
PR219  0_5%  [R0402]  112.68 148.84 90 top
PR220  10K_1%  [R0402]  110.02 140.59 0 top
PR221  100_1%  [R0402]  112.68 139.06 90 top
PR222  100_1%  [R0402]  110.02 139.57 0 top
PR223  SHORT-PAD-10  [R0402_S10MIL_MVB]  112.17 140.59 0 top
PR224  52.3K_1%  [R0402]  110.02 138.56 0 top
PR230  4.7K_5%  [R0402]  7.4 38.73 270 top
PR231  4.7K_5%  [R0402]  12.48 42.8 270 top
PR232  330_1%  [R0603]  15.15 34.67 180 top
PR233  8.2K_1%  [R0402]  22.1 43.15 0 top
PR234  100K_1%  [R0402]  16.92 66.17 180 top
PR235  100K_1%  [R0402]  48.67 63.88 0 top
PR236  10K_5%  [R0402]  36.23 62.1 0 top
PR237  10_1%  [R0402]  16.8 63.63 90 top
PR238  15.4K_1%  [R0402]  48.67 62.87 0 top
PR239  10_1%  [R0402]  51.21 63.37 270 top
PR240  1K_5%  [R0402]  7.53 65.53 90 top
PR241  1K_5%  [R0402]  8.54 65.53 90 top
PR242  1K_5%  [R0402]  51.21 58.55 270 top
PR243  10K_5%  [R0402]  118.78 39.75 0 top
PR244  10K_5%  [R0402]  121.32 37.21 180 top
PR245  10_1%  [R0402]  52.99 33.78 180 top
PR246  10_1%  [R0402]  111.92 31.62 0 top
PR248  1K_5%  [R0402]  110.9 37.21 90 top
PR249  1K_5%  [R0402]  109.89 37.21 90 top
PR250  1.5K_1%  [R0402]  50.96 32.77 0 top
PR252  10K_5%  [R0402]  52.99 32.77 180 top
PR254  4.7K_5%  [R0402]  61.12 34.54 90 top
PR256  2.2_5%  [R0805]  50.07 55.37 180 top
PR257  2.2_5%  [R0805]  40.42 54.48 0 top
PR258  2.2_5%  [R0805]  50.96 46.99 270 top
PR259  2.2_5%  [R0805]  39.02 46.48 0 top
PR260  10K_5%  [R0402]  53.5 46.99 0 top
PR261  10K_5%  [R0402]  36.36 46.86 180 top
PR262  2.2_5%  [R0805]  50.07 53.59 0 top
PR263  2.2_5%  [R0805]  57.82 55.12 180 top
PR264  2.2_5%  [R0805]  38.26 49.02 90 top
PR265  13.3K_1%  [R0402]  47.4 46.48 90 top
PR266  15K_1%  [R0402]  44.23 46.61 90 top
PR267  20K_1%  [R0402]  48.29 46.48 270 top
PR268  0_5%  [R0402]  49.18 46.48 270 top
PR269  10K_5%  [R0402]  49.69 49.91 180 top
PR270  9.76K_1%  [R0402]  42.45 46.61 270 top
PR271  0_5%  [R0402]  41.56 46.61 270 top
PR272  200_5%  [R0402]  40.42 51.82 180 top
PR273  91K_1%  [R0402]  41.82 48.13 180 top
PR274  39.2K_1%  [R0402]  47.66 48.51 270 top
PR275  0_5%  [R0402]  42.96 49.66 270 top
PR276  SHORT-PAD-10  [R0402_S10MIL_MVB]  40.42 50.93 180 top
PR279  10K_5%  [R0402]  106.46 67.06 180 top
PR282  40.2K_1%  [R0402]  108.87 68.07 0 top
PR283  0_5%  [R0402]  108.87 66.04 180 top
PR284  18.7K_1%  [R0402]  108.87 67.06 180 top
PR317  0_5%  [R0402]  232.44 57.02 0 top
PR320  SHORT-PAD-10  [R0402_S10MIL_MVB]  67.47 74.55 0 top
PR336  10K_5%  [R0402]  8.29 43.81 270 top
PR337  33_5%  [R0402]  5.24 45.34 180 top
PR344  10K_1%  [R0402]  93.12 252.09 0 top
PR345  15K_1%  [R0402]  92.62 253.62 90 top
PR347  10K_5%  [R0402]  218.73 73.79 0 top
PR348  10_1%  [R0402]  18.45 73.79 0 top
PR353  10K_5%  [R0402]  60.49 74.29 270 top
PR358  0_5%  [R0402]  108.62 70.61 90 top
PR361  4.7K_5%  [R0402]  236.13 62.48 180 top
PR380  2.2_5%  [R0805]  100.62 75.44 0 top
PR381  10K_5%  [R0402]  109.63 70.61 270 top
PR382  0_5%  [R0402]  233.97 56.51 270 top
PR383  1.5K_1%  [R0402]  112.81 29.34 180 top
PR384  10_5%  [R0805]  102.52 67.44 180 top
PR385  16.2K_1%  [R0402]  106.46 70.1 0 top
PR386  4.7K_5%  [R0402]  105.82 65.41 0 top
PR387  10K_5%  [R0402]  103.67 63.37 90 top
PR388  4.7K_5%  [R0402]  229.52 58.93 180 top
PR389  10K_5%  [R0402]  232.95 55.5 90 top
PR391  0_5%  [R0402]  229.14 57.4 270 top
PR392  10K_5%  [R0402]  231.94 55.5 90 top
PRT1  100K_+/-1%  [R0402]  206.71 196.47 270 top
PRT2  100K_+/-1%  [R0402]  213.52 173.86 0 top
PRT3  100K_+/-1%  [R0402]  206.15 214.63 0 top
PRT4  100K_+/-1%  [R0402]  228.51 170.43 0 top
PU2  RT8237EZQW  [DFN10C]  212.12 71.5 90 top
PU3  RT9045AGSP  [SOP8JA-THP]  153.83 69.85 90 top
PU5  AOZ2262QI-18  [QFN_23_20_157]  66.2 79.88 90 top
PU6  AZ34063UMTR-G1  [SOP8JA]  8.29 220.73 180 top
PU7  RT3607CEGQW  [WQFN_56_16_236_TH174]  222.35 190.94 0 top
PU8  RT9624DGQWA  [DFN8C2]  217.46 209.17 90 top
PU9  RT9624DGQWA  [DFN8C2]  191.3 209.8 90 top
PU10  RT9624DGQWA  [DFN8C2]  174.15 205.99 90 top
PU11  RT9624DGQWA  [DFN8C2]  229.27 159.64 90 top
PU12  RT9624DGQWA  [DFN8C2]  228.76 142.37 90 top
PU13  RT8237EZQW  [DFN10C]  141.38 198.25 0 top
PU14  APL5611CI-TRG  [SOT23_6]  107.22 139.32 90 top
PU16  RT6576DGQW(2)  [QFN_20_16_118X118]  45.63 51.82 90 top
PU18  RT7296FGJ8F  [SOT23_8_H39]  102.9 69.98 0 top
PU20  RT9742CGJ5F  [TSOT23_5_H39]  93 249.3 270 top
PU21  74LVC1G17SE-7  [SOT353_5]  6 43.56 180 top
PWR_SW  Tact Switch_Black  [SW_4_268X303_LED_A]  213 15.25 180 top
Q3  DMN65D8L-7  [SOT23_GSD]  224.7 28.32 0 top
Q99  FDV301N  [SOT23_GSD]  219.11 239.01 90 top
Q104  FDV301N  [SOT23_GSD]  222.92 239.01 90 top
QA3  2N7002P  [SOT23_GSD]  172.75 34.75 180 top
QA4  2N7002P  [SOT23_GSD]  172.63 28.15 0 top
QF1  DMN65D8L-7  [SOT23_GSD]  31.28 100.2 90 top
QF2  2DB1184Q-13  [TO252_BCE_H94]  208.91 225.04 90 top
QG1  BSS138LT1G  [SOT23_GSD]  145.19 218.06 0 top
QL4  MMBT3904-7-F  [SOT23_BEC]  55.53 252.73 90 top
QL5  MMBT3904-7-F  [SOT23_BEC]  58.96 252.73 90 top
QL6  MMBT3904-7-F  [SOT23_BEC]  62.39 252.73 90 top
QL7  FDN308P  [SOT23_GSD_H43]  69.5 252.48 0 top
QM1  MMBT3904-7-F  [SOT23_BEC]  99.73 141.48 0 top
QM2  MMDT3904-7-F  [SOT363V]  110.78 134.24 180 top
QO1  MMDT3904-7-F  [SOT363V]  202.34 45.34 180 top
QO2  MMDT3904-7-F  [SOT363V]  202.47 48.26 180 top
QO3  MMDT3904-7-F  [SOT363V]  9.43 71.63 90 top
QO4  MMDT3904-7-F  [SOT363V]  202.22 51.31 90 top
QO5  MMDT3904-7-F  [SOT363V]  213.14 58.8 90 top
QO6  MMDT3904-7-F  [SOT363V]  201.33 14.18 0 top
QO12  MMDT3904-7-F  [SOT363V]  219.43 16.18 90 top
QO14  MMDT3904-7-F  [SOT363V]  219.55 20.75 270 top
QS10  MMBT3906-7-F  [SOT23_BEC]  147.18 40.79 180 top
QS11  DMN65D8LDW-7  [SOT363M]  215.68 58.8 270 top
QV22  FDV301N  [SOT23_GSD]  218.43 244.73 270 top
QV49  FDV301N  [SOT23_GSD]  228.72 241.83 90 top
QV72  DMN65D8L-7  [SOT23_GSD]  210.09 59.06 90 top
R1  1K_5%  [R0402]  127.2 195.66 90 top
R2  220_5%  [R0402]  194.73 174.88 180 top
R3  1.5K_1%  [R0402]  215.55 34.54 270 top
R7  56.2_1%  [R0402]  197.4 174.88 180 top
R8  100_1%  [R0402]  197.4 173.86 180 top
R9  90.9_1%  [R0402]  197.4 175.89 180 top
R12  1K_5%  [R0402]  128.21 195.66 90 top
R15  1K_5%  [R0402]  117.9 207.64 270 top
R16  1K_5%  [R0402]  118.79 207.64 270 top
R17  1K_5%  [R0402]  119.8 207.64 270 top
R19  8.2K_5%  [R0402]  37.37 123.06 270 top
R20  4.7K_5%  [R0402]  33.05 118.24 180 top
R21  1K_5%  [R0402]  120.82 207.52 270 top
R22  1K_5%  [R0402]  123.61 207.52 270 top
R25  1K_5%  [R0402]  124.88 207.52 270 top
R26  1K_5%  [R0402]  125.9 207.52 270 top
R27  1K_5%  [R0402]  127.09 207.52 270 top
R30  1K_5%  [R0402]  116.88 207.64 270 top
R31  1K_5%  [R0402]  115.99 207.64 270 top
R33  1K_5%  [R0402]  122.6 207.52 270 top
R37  1K_5%  [R0402]  121.71 207.52 270 top
R38  1K_5%  [R0402]  126.31 195.33 90 top
R39  1K_5%  [R0402]  122.85 192.79 90 top
R40  1K_5%  [R0402]  122.75 195.33 90 top
R45  1K_5%  [R0402]  123.64 195.33 90 top
R46  1K_5%  [R0402]  124.53 195.33 90 top
R47  1K_5%  [R0402]  125.42 195.33 90 top
R48  51_5%  [R0402]  121.86 195.33 270 top
R49  49.9_1%  [R0402]  158.78 151.51 90 top
R50  20_5%  [R0402]  121.32 142.11 180 top
R51  1K_5%  [R0402]  136.69 178.31 0 top
R52  51_5%  [R0402]  197.4 176.91 180 top
R60  240_1%  [R0402]  143.59 75.25 90 top
R61  1K_1%  [R0402]  217.33 75.44 90 top
R62  SHORT-PAD-10  [R0402_S10MIL_MVB]  219.24 75.44 90 top
R63  2_1%  [R0402]  223.81 75.44 270 top
R65  1K_1%  [R0402]  218.35 75.44 270 top
R67  8.2K_5%  [R0402]  60.99 104.52 90 top
R68  8.2K_5%  [R0402]  62.39 104.52 90 top
R69  4.7K_5%  [R0402]  48.55 106.68 90 top
R70  10K_5%  [R0402]  47.4 109.22 270 top
R71  4.7K_5%  [R0402]  47.4 104.39 270 top
R72  20K_5%  [R0402]  47.4 106.68 90 top
R73  SHORT-PAD-4  [R0402_S4MIL_MVB]  28.23 129.79 0 top
R74  1K_5%  [R0402]  33.05 115.19 0 top
R75  10K_5%  [R0402]  35.34 115.19 0 top
R77  4.7K_5%  [R0402]  33.05 116.2 180 top
R78  10K_5%  [R0402]  42.83 115.82 0 top
R79  1K_5%  [R0402]  33.05 117.22 0 top
R80  1K_5%  [R0402]  35.85 117.73 90 top
R81  1K_5%  [R0402]  40.55 113.16 0 top
R82  10K_5%  [R0402]  42.83 116.84 0 top
R83  1K_5%  [R0402]  42.83 114.94 0 top
R85  10K_5%  [R0402]  50.83 104.39 90 top
R86  2.2K_5%  [R0402]  132.88 195.58 90 top
R87  2.2K_5%  [R0402]  129.1 207.39 270 top
R88  1K_5%  [R0402]  125.27 192.02 180 top
R89  1K_5%  [R0402]  129.15 195.66 90 top
R90  0_5%  [R0402]  50.83 109.22 90 top
R91  10K_5%  [R0402]  50.83 102.11 270 top
R92  3.3K_5%  [R0402]  123.74 192.79 90 top
R93  33_5%  [R0402]  133.89 195.58 90 top
R96  0_5%  [R0402]  129.99 207.39 270 top
R97  1K_5%  [R0402]  119.72 195.33 90 top
R98  0_5%  [R0402]  50.83 106.68 270 top
R99  10K_5%  [R0402]  51.98 104.39 90 top
R100  10K_5%  [R0402]  49.31 104.27 90 top
R101  0_5%  [R0402]  51.98 109.22 90 top
R102  33_5%  [R0402]  38.51 117.86 180 top
R103  0_5%  [R0402]  49.56 109.22 90 top
R104  10K_5%  [R0402]  48.93 102.49 180 top
R105  10K_5%  [R0402]  51.98 102.11 270 top
R106  24.9_1%  [R0402]  225.84 75.44 270 top
R108  0_5%  [R0402]  49.56 106.68 270 top
R109  0_5%  [R0402]  51.98 106.68 270 top
R112  10K_5%  [R0402]  54.26 104.39 270 top
R114  33_5%  [R0402]  38.13 120.4 0 top
R116  1K_5%  [R0402]  120.44 193.04 90 top
R117  51_5%  [R0402]  131.99 207.39 270 top
R118  0_5%  [R0603]  131.28 195.96 270 top
R119  0_5%  [R0603]  135.39 206.29 0 top
R121  0_5%  [R0402]  136.05 208.03 90 top
R148  0_5%  [R0402]  121.33 193.04 270 top
R149  0_5%  [R0402]  120.74 195.33 270 top
R152  51_5%  [R0402]  135.03 195.58 270 top
R381  680_5%  [R0402]  161.58 238.96 270 top
R495  8.2K_5%  [R0402]  206.15 43.31 0 top
R497  8.2K_5%  [R0402]  206.15 44.32 0 top
R508  8.2K_5%  [R0402]  218.98 57.53 270 top
R663  10K_5%  [R0402]  55.15 83.31 180 top
R6255  1K_5%  [R0402]  138.72 175.51 0 top
R6289  24.9_1%  [R0402]  157.77 151.51 90 top
R6290  24.9_1%  [R0402]  156.75 151.51 90 top
R6296  10.5K_1%  [R0402]  119.29 141.1 180 top
R6298  2.67K_1%  [R0402]  119.29 142.11 180 top
R6331  1K_5%  [R0402]  57.06 139.45 90 top
R6339  11_5%  [R0402]  38.64 138.56 270 top
R6341  33_5%  [R0402]  37.63 138.56 270 top
R6346  56_5%  [R0402]  41.05 136.14 270 top
R6347  22_5%  [R0402]  40.04 136.14 270 top
R6348  11_5%  [R0402]  36.23 138.56 270 top
R6350  33_5%  [R0402]  49.18 141.99 270 top
R6351  33_5%  [R0402]  50.45 139.45 270 top
R6352  8.2K_5%  [R0402]  36.48 123.06 90 top
R6369  10K_5%  [R0402]  31.02 129.41 0 top
R6375  SHORT-PAD-4  [R0402_S4MIL_MVB]  30.64 121.79 0 top
R6378  SHORT-PAD-4  [R0402_S4MIL_MVB]  30.64 122.68 0 top
R6380  SHORT-PAD-4  [R0402_S4MIL_MVB]  30.51 123.57 0 top
R6383  SHORT-PAD-4  [R0402_S4MIL_MVB]  33.56 123.19 0 top
R6388  SHORT-PAD-4  [R0402_S4MIL_MVB]  33.56 124.08 0 top
R6391  10K_5%  [R0402]  34.45 128.27 180 top
R6392  8.2K_5%  [R0402]  35.59 123.06 90 top
R6393  22_5%  [R0402]  32.29 127.13 0 top
R6394  22_5%  [R0402]  32.29 125.09 0 top
R6403  10K_5%  [R0402]  33.56 122.3 0 top
R6408  0_5%  [R0402]  51.21 141.99 90 top
R6413  10K_5%  [R0402]  42.83 123.57 0 top
R6418  47_5%  [R0402]  40.29 142.11 90 top
R6423  10_5%  [R0402]  38.9 127.38 180 top
R6425  20K_5%  [R0402]  39.4 129.03 270 top
R6427  10K_5%  [R0402]  41.31 139.45 90 top
R6431  2.2K_5%  [R0402]  42.32 139.45 90 top
R6434  560_5%  [R0402]  55.02 139.45 90 top
R6435  10K_5%  [R0402]  36.23 126.49 270 top
R6438  8.2K_5%  [R0402]  34.32 129.79 90 top
R6442  30_5%  [R0402]  25.69 129.67 180 top
R6453  1K_5%  [R0603]  174.66 54.99 180 top
R6464  2.7K_1%  [R0402]  67.34 139.95 270 top
R6465  100_1%  [R0402]  71.15 127.51 90 top
R6466  113_1%  [R0402]  57.06 141.99 90 top
R6467  20K_5%  [R0402]  38.39 129.03 90 top
R6468  10M_5%  [R0603]  42.45 132.31 0 top
R6469  1M_1%  [R0402]  71.28 135.25 90 top
R6471  0_5%  [R0603]  54.39 147.07 270 top
R6472  0_5%  [R0603]  70.9 110.36 180 top
R6473  0_5%  [R0603]  64.8 143 0 top
R6500  0_5%  [R0402]  157.26 141.86 0 top
R6513  0_5%  [R0603]  102.65 97.41 0 top
R6518  10K_5%  [R0402]  42.83 117.86 180 top
R6523  SHORT-PAD-4  [R0402_S4MIL_MVB]  226.09 37.47 270 top
R6531  10K_5%  [R0402]  226.98 50.16 0 top
R6533  10K_5%  [R0402]  54.77 87.88 180 top
R6538  22_5%  [R0402]  231.05 240.66 90 top
R6539  100K_5%  [R0402]  171.1 31.32 0 top
R6540  100K_5%  [R0402]  174.28 31.96 270 top
R6541  100K_5%  [R0402]  171.1 30.31 0 top
R6544  1K_5%  [R0402]  35.21 129.79 270 top
R6546  0_5%  [R0402]  114.46 139.57 180 top
R6566  SHORT-PAD-15  [R0603_S15MIL_MVB]  38.51 119.25 180 top
R6568  SHORT-PAD-15  [R0603_S15MIL_MVB]  42.45 111.89 180 top
R6573  10K_5%  [R0402]  57.44 102.23 90 top
R6574  0_5%  [R0402]  134.02 208.03 270 top
R6575  SHORT-PAD-4  [R0402_S4MIL_MVB]  115.73 193.93 270 top
R6576  100_5%  [R0402]  194.72 176.91 180 top
R6577  SHORT-PAD-4  [R0402_S4MIL_MVB]  194.73 173.86 180 top
R6578  SHORT-PAD-4  [R0402_S4MIL_MVB]  194.73 175.89 180 top
R6579  1K_5%  [R0402]  217.2 134.37 180 top
R6580  20_5%  [R0402]  136.18 176.4 270 top
R6581  30_5%  [R0402]  54.01 139.45 90 top
R6582  1K_5%  [R0402]  52.36 141.99 90 top
R6585  1K_5%  [R0402]  55.41 142.05 270 top
R6586  10K_5%  [R0402]  30.01 125.98 0 top
R6590  1.5K_5%  [R0402]  170.59 54.23 270 top
R6591  45.3K_1%  [R0402]  172.12 54.74 0 top
R6595  51_5%  [R0402]  133 207.39 90 top
R6596  30_5%  [R0402]  50.2 141.99 90 top
R6602  1K_5%  [R0402]  56.04 139.45 90 top
R6603  0_5%  [R0402]  56.17 109.35 90 top
R6604  10K_5%  [R0402]  56.17 104.52 90 top
R6605  0_5%  [R0402]  57.44 106.81 90 top
R6606  10K_5%  [R0402]  57.44 104.52 90 top
R6607  10K_5%  [R0402]  56.17 106.81 90 top
R6608  10K_5%  [R0402]  56.17 102.23 270 top
R6613  30_5%  [R0402]  128.68 169.55 180 top
R6614  20_5%  [R0402]  133.26 178.05 180 top
R6615  22_5%  [R0402]  32.29 126.11 0 top
R6618  8.2K_5%  [R0402]  62.39 102.11 270 top
R6619  8.2K_5%  [R0402]  75.98 220.34 90 top
R6628  100K_1%  [R0402]  222.28 31.24 270 top
R6636  100K_5%  [R0402]  145.72 220.34 180 top
R6638  SHORT-PAD-15  [R0603_S15MIL_MVB]  175.3 154.81 0 bottom
R6639  SHORT-PAD-15  [R0603_S15MIL_MVB]  175.3 140.72 90 bottom
R6640  SHORT-PAD-15  [R0603_S15MIL_MVB]  173.4 140.72 90 bottom
R6641  SHORT-PAD-15  [R0603_S15MIL_MVB]  176.82 142.88 90 bottom
R6642  1K_5%  [R0402]  38.39 112.14 270 top
R6643  1K_5%  [R0402]  30.01 103.89 180 top
R6649  10K_5%  [R0402]  41.31 124.08 90 top
R6655  22_5%  [R0402]  27.47 116.84 90 top
R6658  8.2K_5%  [R0402]  37.12 126.49 270 top
R6659  0_5%  [R0402]  130.84 209.42 270 top
R6660  SHORT-PAD-4  [R0402_S4MIL_MVB]  28.23 130.68 180 top
R6661  SHORT-PAD-4  [R0402_S4MIL_MVB]  35.09 126.49 90 top
R6662  SHORT-PAD-4  [R0402_S4MIL_MVB]  34.07 126.49 90 top
R6663  SHORT-PAD-4  [R0402_S4MIL_MVB]  39.78 124.59 0 top
R6664  10K_5%  [R0402]  36.23 128.78 90 top
R6665  10K_5%  [R0402]  217.2 133.35 180 top
R6668  8.2K_5%  [R0402]  66.33 104.9 90 top
R6669  8.2K_5%  [R0402]  65.44 109.47 90 top
R6680  51_5%  [R0402]  135.03 208.03 270 top
R6681  0_5%  [R0402]  119.03 196.72 180 top
R6682  0_5%  [R0402]  128.56 192.79 90 top
RA1  100K_5%  [R0402]  181.64 15.32 270 top
RA2  0_5%  [R0402]  171.74 22.18 180 top
RA4  20K_5%  [R0402]  176.44 32.97 90 top
RA5  20K_5%  [R0402]  177.45 32.97 90 top
RA6  20K_5%  [R0402]  176.44 30.94 270 top
RA7  0_5%  [R0402]  186.72 30.18 270 top
RA8  0_5%  [R0402]  191.55 31.2 270 top
RA9  20K_5%  [R0402]  34.83 117.73 270 top
RA10  20K_5%  [R0402]  40.55 116.84 180 top
RA11  20K_5%  [R0402]  40.55 115.82 180 top
RA12  20K_5%  [R0402]  35.34 116.2 180 top
RA13  20K_5%  [R0402]  40.55 117.86 180 top
RA14  20K_5%  [R0402]  40.55 114.94 180 top
RA15  100K_1%  [R0402]  178.09 27.39 180 top
RA16  200K_1%  [R0402]  180.12 27.39 180 top
RA17  100K_1%  [R0402]  178.6 28.91 90 top
RA18  100K_1%  [R0402]  179.61 28.91 90 top
RA19  SHORT-PAD-4  [R0402_S4MIL_MVB]  185.71 33.48 270 top
RA20  39_5%  [R0402]  183.04 33.48 90 top
RA21  100K_1%  [R0402]  190.66 28.4 180 top
RA22  1K_5%  [R0402]  191.04 29.67 180 top
RA33  51K_1%  [R0402]  201.07 18.24 0 top
RA34  1K_1%  [R0402]  200.57 16.72 270 top
RA35  56K_1%  [R0402]  201.58 16.72 270 top
RA36  0_5%  [R0402]  190.53 31.2 270 top
RA37  100K_5%  [R0402]  188.25 30.69 180 top
RA40  1K_5%  [R0402]  175.04 17.35 270 top
RA41  1K_5%  [R0402]  176.06 17.35 270 top
RA42  0_5%  [R0402]  191.35 17.86 135 top
RA43  0_5%  [R0402]  195.36 18.5 0 top
RA44  0_5%  [R0402]  231.94 234.06 180 top
RA58  10K_5%  [R0402]  175.42 31.96 270 top
RA59  20K_5%  [R0402]  42.83 113.16 0 top
RA69  10K_5%  [R0402]  62.39 107.06 270 top
RA70  75_1%  [R0402]  233.46 234.95 90 top
RA71  75_1%  [R0402]  234.48 234.95 90 top
RA72  2.2K_5%  [R0402]  175.67 26.62 0 top
RA73  2.2K_5%  [R0402]  175.67 23.07 180 top
RA74  18_1%  [R0402]  189.52 8.34 90 top
RA75  18_1%  [R0402]  188.5 8.34 90 top
RA76  4.7K_5%  [R0402]  186.47 15.83 0 top
RA77  4.7K_5%  [R0402]  186.5 17.14 0 top
RB1  0_5%  [R0402]  12.86 185.42 180 top
RB2  0_5%  [R0402]  7.78 181.61 0 top
RB3  0_5%  [R0402]  12.86 190.88 180 top
RB4  0_5%  [R0402]  12.86 200.28 180 top
RB5  0_5%  [R0402]  12.86 199.26 180 top
RB6  0_5%  [R0402]  12.86 201.29 180 top
RB7  0_5%  [R0402]  12.86 187.2 0 top
RB8  0_5%  [R0402]  12.23 183.64 0 top
RB9  0_5%  [R0402]  12.86 188.21 0 top
RB10  0_5%  [R0402]  12.86 191.9 0 top
